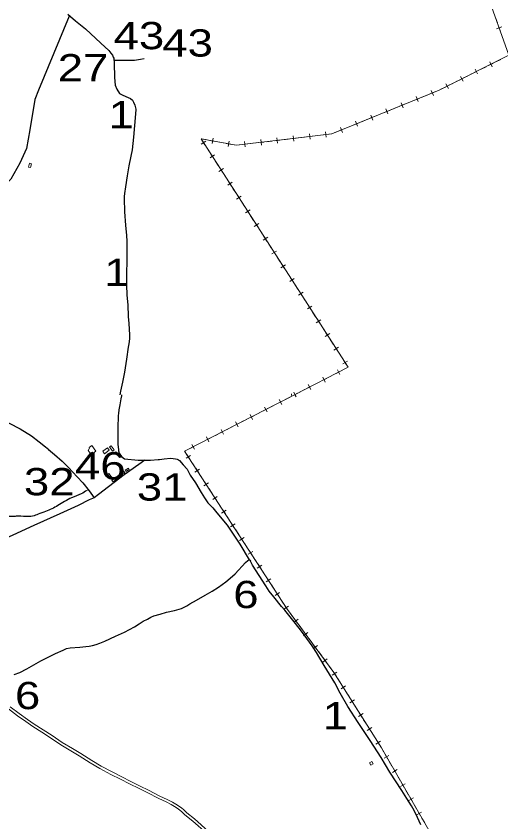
# Model space of a CAD drawing. Extents: x 476989 to 498418, y 4381813 to 4416555.
# Drawn here: x 486771 to 487660, y 4385659 to 4387137 of the extents above; entities that cross this region are included whole.
import ezdxf
from ezdxf.enums import TextEntityAlignment as Align

# ---------------------------------------------------------------- set-up
doc = ezdxf.new("R2010")
doc.units = 0
doc.header["$LTSCALE"] = 20
doc.linetypes.add('MEDIUM_DASHED', pattern=[4.5, 3, -1.5])
for name, color, linetype, lineweight in [('13', 7, 'Continuous', 13), ('34', 7, 'Continuous', 13), ('36', 7, 'Continuous', 13), ('38', 7, 'Continuous', 13), ('47', 7, 'Continuous', 13), ('48', 7, 'MEDIUM_DASHED', 13), ('54', 7, 'Continuous', 13), ('6', 7, 'Continuous', 25)]:
    doc.layers.add(name, color=color, linetype=linetype, lineweight=lineweight)

msp = doc.modelspace()

# ---------------------------------------------------------------- linework, layer by layer
at = {"layer": '34'}
for p, q in [((487650.55, 4387134.18), (487653.88, 4387124.75)), ((487661.92, 4387117), (487652.5, 4387113.67)), ((487655.54, 4387120.05), (487658.88, 4387110.62)), ((487660.16, 4387057.58), (487651.21, 4387053.11)), ((487633.33, 4387044.17), (487624.39, 4387039.69)), ((487646.75, 4387050.87), (487637.8, 4387046.4)), ((487644.51, 4387044.17), (487640.04, 4387053.11)), ((487590.87, 4387017.34), (487586.39, 4387026.29)), ((487606.51, 4387030.75), (487597.56, 4387026.28)), ((487619.92, 4387037.46), (487610.98, 4387032.99)), ((487617.69, 4387030.75), (487613.22, 4387039.7)), ((487566.28, 4387010.64), (487557.33, 4387006.17)), ((487564.04, 4387003.93), (487559.57, 4387012.87)), ((487579.68, 4387017.34), (487570.74, 4387012.87)), ((487593.1, 4387024.05), (487584.16, 4387019.58)), ((487539.18, 4386997.83), (487529.92, 4386994.06)), ((487536.43, 4386991.31), (487532.67, 4387000.58)), ((487497.5, 4386980.9), (487488.23, 4386977.14)), ((487511.4, 4386986.54), (487502.13, 4386982.78)), ((487508.64, 4386980.03), (487504.88, 4386989.29)), ((487525.28, 4386992.18), (487516.02, 4386988.42)), ((487453.07, 4386957.46), (487449.31, 4386966.73)), ((487469.71, 4386969.61), (487460.45, 4386965.85)), ((487483.61, 4386975.26), (487474.34, 4386971.5)), ((487480.86, 4386968.74), (487477.1, 4386978.01)), ((487428.04, 4386952.69), (487418.77, 4386948.93)), ((487425.29, 4386946.18), (487421.52, 4386955.44)), ((487441.93, 4386958.33), (487432.66, 4386954.57)), ((487455.82, 4386963.97), (487446.56, 4386960.21)), ((487400.25, 4386941.41), (487390.99, 4386937.64)), ((487397.5, 4386934.89), (487393.74, 4386944.16)), ((487414.14, 4386947.05), (487404.87, 4386943.28)), ((487339.93, 4386914.76), (487338.74, 4386924.68)), ((487372.46, 4386930.12), (487363.2, 4386926.36)), ((487369.71, 4386923.61), (487365.95, 4386932.87)), ((487386.35, 4386935.76), (487377.09, 4386932)), ((487118.7, 4386907.72), (487110.3, 4386902.31)), ((487121.49, 4386909.88), (487111.65, 4386911.69)), ((487111.79, 4386909.22), (487117.21, 4386900.81)), ((487136.24, 4386907.16), (487126.4, 4386908.97)), ((487130.41, 4386903.15), (487132.23, 4386912.98)), ((487159.9, 4386897.7), (487161.72, 4386907.54)), ((487220.82, 4386900.46), (487219.63, 4386910.39)), ((487240.08, 4386907.81), (487230.15, 4386906.62)), ((487254.97, 4386909.6), (487245.04, 4386908.4)), ((487250.6, 4386904.04), (487249.41, 4386913.96)), ((487269.85, 4386911.38), (487259.92, 4386910.19)), ((487284.74, 4386913.17), (487274.82, 4386911.98)), ((487280.38, 4386907.61), (487279.18, 4386917.54)), ((487299.63, 4386914.96), (487289.7, 4386913.76)), ((487314.52, 4386916.74), (487304.59, 4386915.55)), ((487310.15, 4386911.18), (487308.96, 4386921.11)), ((487329.4, 4386918.53), (487319.48, 4386917.34)), ((487344.3, 4386920.32), (487334.37, 4386919.12)), ((487119.92, 4386896.61), (487125.33, 4386888.2)), ((487150.98, 4386904.43), (487141.14, 4386906.25)), ((487165.73, 4386901.71), (487155.9, 4386903.53)), ((487195.42, 4386902.45), (487185.49, 4386901.26)), ((487191.05, 4386896.89), (487189.86, 4386906.82)), ((487210.3, 4386904.24), (487200.37, 4386903.04)), ((487225.19, 4386906.02), (487215.26, 4386904.83)), ((487134.95, 4386882.51), (487126.54, 4386877.1)), ((487128.04, 4386884.01), (487133.45, 4386875.6)), ((487136.16, 4386871.4), (487141.58, 4386862.99)), ((487151.19, 4386857.3), (487142.79, 4386851.89)), ((487144.28, 4386858.8), (487149.7, 4386850.39)), ((487152.41, 4386846.19), (487157.82, 4386837.78)), ((487160.53, 4386833.59), (487165.94, 4386825.18)), ((487167.44, 4386832.1), (487159.03, 4386826.68)), ((487168.65, 4386820.98), (487174.07, 4386812.58)), ((487183.68, 4386806.89), (487175.28, 4386801.47)), ((487176.77, 4386808.38), (487182.19, 4386799.97)), ((487184.9, 4386795.77), (487190.31, 4386787.37)), ((487199.93, 4386781.68), (487191.52, 4386776.26)), ((487193.02, 4386783.17), (487198.43, 4386774.77)), ((487201.14, 4386770.56), (487206.56, 4386762.16)), ((487216.17, 4386756.47), (487207.77, 4386751.05)), ((487209.26, 4386757.96), (487214.68, 4386749.56)), ((487217.39, 4386745.35), (487222.8, 4386736.95)), ((487232.42, 4386731.26), (487224.01, 4386725.84)), ((487225.51, 4386732.75), (487230.92, 4386724.35)), ((487233.63, 4386720.14), (487239.05, 4386711.74)), ((487248.66, 4386706.05), (487240.26, 4386700.63)), ((487241.75, 4386707.54), (487247.17, 4386699.14)), ((487249.88, 4386694.93), (487255.29, 4386686.53)), ((487264.91, 4386680.84), (487256.5, 4386675.42)), ((487257.99, 4386682.33), (487263.41, 4386673.93)), ((487266.12, 4386669.73), (487271.54, 4386661.32)), ((487274.24, 4386657.12), (487279.66, 4386648.72)), ((487281.15, 4386655.63), (487272.74, 4386650.21)), ((487282.36, 4386644.52), (487287.78, 4386636.11)), ((487297.4, 4386630.42), (487288.99, 4386625)), ((487290.48, 4386631.92), (487295.9, 4386623.51)), ((487298.61, 4386619.31), (487304.03, 4386610.9)), ((487313.64, 4386605.21), (487305.23, 4386599.79)), ((487306.73, 4386606.71), (487312.15, 4386598.3)), ((487314.85, 4386594.1), (487320.27, 4386585.69)), ((487329.88, 4386580), (487321.48, 4386574.59)), ((487322.97, 4386581.5), (487328.39, 4386573.09)), ((487331.1, 4386568.89), (487336.52, 4386560.48)), ((487346.13, 4386554.79), (487337.72, 4386549.38)), ((487339.22, 4386556.29), (487344.63, 4386547.88)), ((487347.34, 4386543.68), (487352.76, 4386535.27)), ((487362.37, 4386529.58), (487353.97, 4386524.17)), ((487355.46, 4386531.08), (487360.88, 4386522.67)), ((487363.59, 4386518.47), (487369, 4386510.06)), ((487378.62, 4386504.37), (487370.21, 4386498.96)), ((487371.71, 4386505.87), (487377.12, 4386497.46)), ((487353.6, 4386479.45), (487344.7, 4386474.88)), ((487366.94, 4386486.3), (487358.04, 4386481.73)), ((487364.77, 4386479.56), (487360.21, 4386488.46)), ((487326.91, 4386465.75), (487318.02, 4386461.18)), ((487340.26, 4386472.6), (487331.36, 4386468.03)), ((487338.09, 4386465.87), (487333.53, 4386474.76)), ((487300.23, 4386452.05), (487291.34, 4386447.49)), ((487313.58, 4386458.9), (487304.68, 4386454.34)), ((487311.41, 4386452.17), (487306.85, 4386461.07)), ((487273.55, 4386438.36), (487264.66, 4386433.79)), ((487280.6, 4386441.97), (487278, 4386440.64)), ((487282.94, 4386441.97), (487280.17, 4386447.37)), ((487286.9, 4386445.21), (487280.6, 4386441.97)), ((487284.73, 4386438.48), (487282.94, 4386441.97)), ((487231.37, 4386411.09), (487226.81, 4386419.98)), ((487246.87, 4386424.66), (487237.98, 4386420.1)), ((487260.22, 4386431.51), (487251.32, 4386426.95)), ((487258.05, 4386424.78), (487253.49, 4386433.68)), ((487204.69, 4386397.39), (487200.13, 4386406.29)), ((487220.19, 4386410.97), (487211.3, 4386406.4)), ((487233.54, 4386417.82), (487224.64, 4386413.25)), ((487180.18, 4386390.43), (487171.28, 4386385.86)), ((487178.01, 4386383.69), (487173.45, 4386392.59)), ((487193.51, 4386397.27), (487184.62, 4386392.7)), ((487206.86, 4386404.12), (487197.96, 4386399.55)), ((487153.5, 4386376.73), (487144.6, 4386372.16)), ((487151.33, 4386370), (487146.77, 4386378.89)), ((487166.83, 4386383.58), (487157.94, 4386379.01)), ((487126.82, 4386363.03), (487117.92, 4386358.47)), ((487124.65, 4386356.3), (487120.09, 4386365.2)), ((487140.15, 4386369.88), (487131.26, 4386365.31)), ((487100.14, 4386349.34), (487091.24, 4386344.77)), ((487097.97, 4386342.61), (487093.41, 4386351.5)), ((487113.47, 4386356.18), (487104.58, 4386351.62)), ((487090.92, 4386331.36), (487082.53, 4386325.92)), ((487084, 4386332.83), (487089.45, 4386324.45)), ((487092.17, 4386320.25), (487097.62, 4386311.87)), ((487107.25, 4386306.21), (487098.87, 4386300.76)), ((487100.34, 4386307.68), (487105.78, 4386299.29)), ((487108.5, 4386295.1), (487113.95, 4386286.71)), ((487123.58, 4386281.06), (487115.2, 4386275.61)), ((487116.67, 4386282.53), (487122.11, 4386274.14)), ((487124.84, 4386269.95), (487130.28, 4386261.56)), ((487133, 4386257.37), (487138.45, 4386248.99)), ((487139.92, 4386255.9), (487131.53, 4386250.46)), ((487141.17, 4386244.79), (487146.61, 4386236.41)), ((487156.25, 4386230.75), (487147.86, 4386225.31)), ((487149.33, 4386232.22), (487154.78, 4386223.83)), ((487157.5, 4386219.64), (487162.95, 4386211.25)), ((487172.58, 4386205.6), (487164.19, 4386200.15)), ((487165.66, 4386207.07), (487171.11, 4386198.68)), ((487173.83, 4386194.49), (487179.28, 4386186.1)), ((487188.91, 4386180.45), (487180.53, 4386175)), ((487182, 4386181.92), (487187.44, 4386173.53)), ((487190.16, 4386169.34), (487195.61, 4386160.95)), ((487205.24, 4386155.29), (487196.86, 4386149.85)), ((487198.33, 4386156.76), (487203.77, 4386148.38)), ((487206.5, 4386144.18), (487211.94, 4386135.8)), ((487221.58, 4386130.14), (487213.19, 4386124.69)), ((487214.66, 4386131.61), (487220.11, 4386123.22)), ((487222.83, 4386119.03), (487228.27, 4386110.64)), ((487237.91, 4386104.99), (487229.52, 4386099.54)), ((487230.99, 4386106.46), (487236.44, 4386098.07)), ((487239.16, 4386093.88), (487244.61, 4386085.49)), ((487254.24, 4386079.83), (487245.85, 4386074.39)), ((487247.32, 4386081.3), (487252.77, 4386072.92)), ((487255.49, 4386068.72), (487260.94, 4386060.34)), ((487270.57, 4386054.68), (487262.18, 4386049.23)), ((487272.26, 4386043.87), (487278.19, 4386035.82)), ((487288.14, 4386030.75), (487280.09, 4386024.81)), ((487281.15, 4386031.81), (487287.09, 4386023.76)), ((487290.05, 4386019.73), (487295.99, 4386011.68)), ((487305.94, 4386006.61), (487297.89, 4386000.67)), ((487298.95, 4386007.67), (487304.88, 4385999.62)), ((487307.85, 4385995.59), (487313.79, 4385987.54)), ((487323.74, 4385982.47), (487315.69, 4385976.54)), ((487316.75, 4385983.53), (487322.68, 4385975.48)), ((487325.65, 4385971.45), (487331.58, 4385963.41)), ((487341.53, 4385958.33), (487333.49, 4385952.4)), ((487334.54, 4385959.39), (487340.48, 4385951.34)), ((487343.44, 4385947.32), (487349.38, 4385939.27)), ((487359.4, 4385933.8), (487350.95, 4385928.47)), ((487360.51, 4385922.68), (487365.84, 4385914.22)), ((487375.4, 4385908.43), (487366.94, 4385903.1)), ((487368.5, 4385910), (487373.84, 4385901.54)), ((487376.5, 4385897.31), (487381.83, 4385888.85)), ((487391.39, 4385883.06), (487382.93, 4385877.73)), ((487384.5, 4385884.63), (487389.83, 4385876.17)), ((487392.5, 4385871.94), (487397.83, 4385863.48)), ((487400.49, 4385859.26), (487405.82, 4385850.8)), ((487407.39, 4385857.69), (487398.93, 4385852.36)), ((487408.49, 4385846.57), (487413.82, 4385838.11)), ((487423.38, 4385832.33), (487414.92, 4385826.99)), ((487416.48, 4385833.89), (487421.82, 4385825.43)), ((487424.48, 4385821.2), (487429.82, 4385812.74)), ((487439.37, 4385806.96), (487430.91, 4385801.62)), ((487432.48, 4385808.52), (487437.81, 4385800.06)), ((487454.83, 4385781.04), (487446.17, 4385776.04)), ((487448, 4385782.87), (487453, 4385774.21)), ((487455.5, 4385769.88), (487460.5, 4385761.22)), ((487469.82, 4385755.06), (487461.16, 4385750.06)), ((487463, 4385756.89), (487467.99, 4385748.23)), ((487470.49, 4385743.9), (487475.49, 4385735.24)), ((487484.82, 4385729.09), (487476.16, 4385724.09)), ((487477.99, 4385730.92), (487482.99, 4385722.26)), ((487485.49, 4385717.93), (487490.48, 4385709.27)), ((487499.81, 4385703.12), (487491.15, 4385698.12)), ((487492.98, 4385704.95), (487497.98, 4385696.29)), ((487500.48, 4385691.96), (487505.48, 4385683.29)), ((487514.8, 4385677.14), (487506.14, 4385672.14)), ((487507.97, 4385678.97), (487512.97, 4385670.31)), ((487515.47, 4385665.98), (487520.47, 4385657.32))]:
    msp.add_line(p, q, dxfattribs=at)
for points in [[(486520.9, 4388755.72), (486603, 4388633), (486612, 4388581), (486746, 4388393), (486776, 4388338), (486812, 4388290), (486879, 4388250), (487017, 4388189), (487152, 4388148), (487234, 4388140), (487360, 4387899), (487497, 4387717), (487531, 4387660), (487608, 4387440), (487634, 4387181), (487675, 4387065), (487547, 4387001), (487350, 4386921), (487175, 4386900), (487110, 4386912), (487380, 4386493), (487280.6, 4386441.97)], [(487552.86, 4387003.93), (487547, 4387001), (487543.81, 4386999.7)], [(487358.57, 4386924.48), (487350, 4386921), (487349.25, 4386920.91)], [(487180.52, 4386900.66), (487175, 4386900), (487170.64, 4386900.81)], [(487379.83, 4386493.26), (487380, 4386493), (487371.38, 4386488.57)], [(487280.6, 4386441.97), (487080, 4386339), (487267, 4386051), (487354, 4385933), (487441, 4385795), (487598, 4385523), (487650, 4385422), (487680.1, 4385371.64)], [(487086.79, 4386342.49), (487080, 4386339), (487081.29, 4386337.02)], [(487263.66, 4386056.15), (487267, 4386051), (487269.29, 4386047.89)], [(487352.34, 4385935.25), (487354, 4385933), (487357.84, 4385926.91)], [(487440.48, 4385795.83), (487441, 4385795), (487445.51, 4385787.19)]]:
    msp.add_lwpolyline(points, dxfattribs=at)
at = {"layer": '36'}
for points in [[(486756.73, 4385866.21), (486773.27, 4385853.94), (486788.78, 4385843.03), (486801.28, 4385834.3), (486817.65, 4385823.74), (486834.02, 4385813.25), (486852.64, 4385800.54), (486871.33, 4385789.79), (486886.69, 4385780.11), (486906.79, 4385767.31), (486924.22, 4385757.28), (486944.54, 4385746.26), (486962.36, 4385737.33), (486978.95, 4385729.07), (486996.26, 4385720.26), (487011.28, 4385712.94), (487032.42, 4385701.79), (487045.82, 4385695.72), (487055.01, 4385691.14), (487061.37, 4385687.37), (487067.84, 4385683.2), (487071.58, 4385680.27), (487074.28, 4385678), (487080.56, 4385672.07), (487094.87, 4385660.71), (487120.03, 4385638.46)], [(486759.77, 4385870.17), (486776.19, 4385857.99), (486791.65, 4385847.12), (486804.07, 4385838.45), (486820.36, 4385827.94), (486836.78, 4385817.42), (486855.3, 4385804.78), (486873.91, 4385794.07), (486889.37, 4385784.33), (486909.38, 4385771.58), (486926.66, 4385761.64), (486946.85, 4385750.69), (486964.59, 4385741.8), (486981.2, 4385733.53), (486998.49, 4385724.73), (487013.54, 4385717.39), (487034.62, 4385706.28), (487047.97, 4385700.24), (487057.41, 4385695.53), (487064, 4385691.62), (487070.75, 4385687.27), (487074.73, 4385684.15), (487077.6, 4385681.73), (487083.83, 4385675.85), (487098.08, 4385664.55), (487123.34, 4385642.2)]]:
    msp.add_lwpolyline(points, dxfattribs=at)
at = {"layer": '38', "linetype": 'MEDIUM_DASHED'}
for p, q in [((487276.18, 4386441.98), (487276.14, 4386444.17)), ((487276.19, 4386441.09), (487276.18, 4386441.98)), ((487277.97, 4386441.08), (487277.84, 4386441.33))]:
    msp.add_line(p, q, dxfattribs=at)
at = {"layer": '38'}
msp.add_line((487277.84, 4386441.08), (487277.84, 4386441.33), dxfattribs=at)
at = {"layer": '47'}
msp.add_lwpolyline([(486916.71, 4386339.17), (486909.73, 4386349.55), (486904.57, 4386345.72), (486905.46, 4386344.81), (486902.77, 4386340.27), (486906.37, 4386335.49), (486910.38, 4386337.38), (486911.85, 4386335.34)], close=True, dxfattribs=at)
at = {"layer": '48'}
for points in [[(486795.28, 4386866.99), (486793.41, 4386860.13), (486797.27, 4386859.08), (486799.14, 4386865.94)], [(487419.36, 4385767.39), (487421.72, 4385763.16), (487425.79, 4385765.43), (487423.43, 4385769.66)]]:
    msp.add_lwpolyline(points, close=True, dxfattribs=at)
at = {"layer": '54'}
for points in [[(486944.91, 4386349.12), (486950.86, 4386341.52), (486947.77, 4386339.1), (486941.82, 4386346.7)], [(486938.33, 4386345.16), (486929.58, 4386338.88), (486932.77, 4386334.44), (486941.52, 4386340.72)], [(486955.08, 4386335.92), (486952.46, 4386334.01), (486951.03, 4386335.98), (486953.65, 4386337.89)], [(486968.03, 4386302.42), (486970.06, 4386299.97), (486968.12, 4386298.36), (486966.09, 4386300.81)], [(486978.35, 4386305.49), (486972.35, 4386301.67), (486970.9, 4386303.95), (486976.9, 4386307.77)], [(486938.52, 4386295.86), (486945.52, 4386287.62), (486947.81, 4386289.57), (486940.81, 4386297.81)], [(486964.25, 4386294.89), (486948.86, 4386282.59), (486946.63, 4386285.39), (486962.02, 4386297.69)]]:
    msp.add_lwpolyline(points, close=True, dxfattribs=at)
at = {"layer": '6'}
msp.add_line((486964.35, 4386442.58), (486964.17, 4386441.69), dxfattribs=at)
for points in [[(486868.26, 4387136.57), (486811.84, 4387000.91), (486805.15, 4386983.72), (486795.59, 4386928.58), (486789.85, 4386894.19), (486777.42, 4386867.44), (486761.17, 4386837.83), (486742.05, 4386817.76), (486701.89, 4386767.13)], [(486865.82, 4387140.44), (486870.56, 4387136.44), (486879.61, 4387128.5), (486897.89, 4387113.26), (486926.12, 4387087.48), (486940.93, 4387073.82), (486944.75, 4387069.02), (486947.51, 4387065.21), (486948.41, 4387063.27), (486948.98, 4387061.46), (486949.78, 4387059.74), (486950.89, 4387050.52), (486951.42, 4387024.29), (486952.31, 4387010.12), (486955.39, 4387002.81), (486960.38, 4386995.17), (486966.75, 4386991.88), (486976.24, 4386987.87), (486980.83, 4386985.8), (486984.46, 4386982.61), (486986.33, 4386978.92), (486988.67, 4386973.34), (486990.07, 4386968.73), (486990.35, 4386966.24), (486990.34, 4386965.73), (486989.85, 4386957.54), (486986.32, 4386914.8), (486984.82, 4386903.45), (486983.61, 4386891.79), (486981.37, 4386879.94), (486977.67, 4386862.56), (486974.46, 4386844.13), (486971.23, 4386823.55), (486969.53, 4386811.81), (486969.07, 4386806.08), (486968.75, 4386799.56), (486968.75, 4386793.59), (486969.4, 4386786.44), (486969.8, 4386777.94), (486971.34, 4386753.69), (486973.54, 4386734.41), (486974.05, 4386723.9), (486973.93, 4386710.67), (486973.72, 4386700.87), (486973.6, 4386692.29), (486973.36, 4386660.37), (486973.36, 4386644.22), (486974.13, 4386624.85), (486975.53, 4386607.28), (486976.28, 4386585.73), (486977.3, 4386573.44), (486977.9, 4386563.02), (486978.72, 4386552.25), (486978.69, 4386545.45), (486977.95, 4386540.19), (486977.6, 4386535.73), (486976.62, 4386529.49), (486973.38, 4386507.65), (486969.33, 4386483.98), (486965.73, 4386465.44)], [(486951.44, 4387056.08), (486988.25, 4387056.08), (486998.77, 4387057.99), (487005.46, 4387059.42)], [(486965.73, 4386465.44), (486962.27, 4386449.05), (486960.98, 4386442.59)], [(486600.64, 4386442.39), (486607.65, 4386440.65), (486631.5, 4386435.51), (486646.21, 4386432.66), (486660.23, 4386428.62), (486673.01, 4386424.84), (486686.48, 4386420.88), (486703.03, 4386415.38), (486723.45, 4386407.12), (486742.44, 4386398.57), (486757.96, 4386390.6), (486777.87, 4386380.02), (486798.8, 4386367.44), (486813.03, 4386356.38), (486824.46, 4386346.9), (486830.71, 4386342.04)], [(486964.17, 4386441.69), (486963.99, 4386440.8), (486963.15, 4386434.82), (486961.03, 4386423.87), (486959.27, 4386415.13), (486958.3, 4386408.14), (486958.03, 4386404.51), (486957.73, 4386399.66), (486957.54, 4386385.95), (486957.43, 4386367.52), (486957.48, 4386355.76), (486957.48, 4386352.52), (486957.89, 4386346.03), (486958.44, 4386342.63), (486958.7, 4386339.75), (486959.71, 4386335.08), (486964.18, 4386329.2), (486969.87, 4386325.21)], [(486830.06, 4386342.28), (486841.31, 4386332.99), (486855.28, 4386320.6), (486866.55, 4386309.08), (486883.05, 4386291.8), (486893.44, 4386280.96), (486904.67, 4386266.03), (486914.04, 4386253.6)], [(487006.7, 4386322.35), (486996.11, 4386314.49), (486969.28, 4386295.81), (486921.9, 4386259.34), (486914.05, 4386253.61), (486904.73, 4386249.79), (486884.67, 4386239.67), (486850.72, 4386224), (486803, 4386202.78), (486764.38, 4386184.86), (486738.63, 4386173.19), (486716.6, 4386163.81), (486698.96, 4386159.51), (486686.97, 4386155.06), (486674.32, 4386151.21), (486667.46, 4386148.9)], [(486969.87, 4386325.21), (486994.51, 4386322.75), (487017.32, 4386322.57), (487031.66, 4386323.49), (487033.84, 4386323.76)], [(487033.84, 4386323.76), (487042.5, 4386325.14), (487053.91, 4386325.94), (487058.85, 4386325.87), (487063.33, 4386324.69), (487066.47, 4386324.42), (487068.98, 4386323.12), (487070.31, 4386321.9), (487077.31, 4386314.01), (487084.56, 4386306.18), (487090.4, 4386295.22), (487099.73, 4386280.83), (487110.28, 4386263.12), (487116.59, 4386253.34), (487122.76, 4386244.17), (487131.94, 4386235.26), (487139.31, 4386226.08), (487158.04, 4386203.31), (487181.5, 4386168.37), (487198.43, 4386139.94)], [(486767.38, 4385929.3), (486777.82, 4385933.01), (486790.63, 4385940.11), (486816.11, 4385954.4), (486842.97, 4385967.98), (486856.8, 4385973.84), (486863.2, 4385976.89), (486870.1, 4385978.29), (486887.62, 4385979.51), (486898.46, 4385980.58), (486904.53, 4385981.38), (486911.03, 4385982.92), (486917.86, 4385984.51), (486924.28, 4385987.17), (486933.54, 4385990.54), (486953.2, 4386000.02), (486969.46, 4386007.19), (486978.94, 4386012.25), (486987.97, 4386017.06), (486996.64, 4386022.22), (487004.16, 4386027.04), (487011.57, 4386031.23), (487017.83, 4386034.46), (487023.45, 4386036.93), (487034.88, 4386040.13), (487046.43, 4386043.6), (487061.36, 4386047.05), (487074.18, 4386050.65), (487079.1, 4386052.94), (487083.98, 4386055.69), (487089.78, 4386059), (487101.5, 4386065.89), (487117.69, 4386075.07), (487130.52, 4386082.16), (487142.14, 4386089.51), (487155.67, 4386099.18), (487163.6, 4386106.12), (487172.67, 4386113.9), (487191.42, 4386135.09), (487195.78, 4386138.66)], [(487195.78, 4386138.66), (487198.43, 4386139.98), (487199.62, 4386138.92), (487200.54, 4386137.06)], [(487513.12, 4385653.9), (487507.22, 4385666.93), (487500.95, 4385680.07), (487496.09, 4385688.73), (487487.69, 4385701.85), (487478.39, 4385717.04), (487456.26, 4385750.25), (487440.58, 4385777.2), (487420.22, 4385808.25), (487398.32, 4385841.52), (487379.63, 4385870.99), (487365.57, 4385895.03), (487355.43, 4385914.12), (487335.81, 4385945.95), (487322.23, 4385970.08), (487314.11, 4385982.06), (487304.47, 4385995.75), (487292.37, 4386011.32), (487278.39, 4386029.12), (487263.61, 4386047.36), (487257.87, 4386054.11), (487243.52, 4386071.62), (487234.89, 4386082.44), (487228.78, 4386092.37), (487204.73, 4386130.27), (487200.54, 4386137.07)]]:
    msp.add_lwpolyline(points, dxfattribs=at)
msp.add_spline([(486900.82, 4386267.12), (486890.15, 4386260.84), (486872.56, 4386253.58), (486847.29, 4386239.24), (486824.78, 4386228.53), (486811.05, 4386223.55), (486801.02, 4386219.94), (486788.56, 4386219.37), (486770.77, 4386219.55), (486762.82, 4386219.44), (486754.86, 4386219.33), (486743.07, 4386218.67), (486738.39, 4386216.56), (486736.71, 4386214.79), (486734.3, 4386213.92), (486729.34, 4386213.24), (486727.91, 4386213.26), (486723.04, 4386213.33), (486719.96, 4386213.3), (486715.82, 4386212.61), (486713.55, 4386211.14), (486709.92, 4386208.94), (486707.34, 4386207.25), (486696.59, 4386205.53), (486687.66, 4386205.36), (486680, 4386205.32), (486677.23, 4386205.43), (486673.7, 4386205.71), (486667.41, 4386206.63), (486664.95, 4386207.19), (486654.69, 4386208.68), (486654.69, 4386208.76)], degree=3, dxfattribs=at)

# ---------------------------------------------------------------- texts
at = {"layer": '13', "width": 1.25}
for s, p in [('43', (486996.07, 4387076.2)), ('43', (487085.41, 4387062.68)), ('27', (486893.56, 4387017.25)), ('1', (486963.59, 4386931.1)), ('1', (486955.68, 4386642.08)), ('46', (486925.16, 4386287.17)), ('32', (486831.46, 4386258.14)), ('31', (487038.72, 4386248.42)), ('6', (487192.42, 4386051.19)), ('6', (486791.76, 4385865.93)), ('1', (487356.58, 4385828.88))]:
    msp.add_text(s, height=50, dxfattribs=at).set_placement(p, align=Align.CENTER)

doc.saveas('drawing.dxf')
